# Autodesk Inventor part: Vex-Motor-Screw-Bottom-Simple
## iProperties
Created: 2007-08
Part Number: Vex-Motor-Screw-Bottom-Simple
Material: Steel
Document SubType Name: Modeling
Density: 7.85 g/cm^3
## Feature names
1. Base1
